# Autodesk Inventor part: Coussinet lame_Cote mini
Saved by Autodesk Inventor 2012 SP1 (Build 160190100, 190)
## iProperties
Created: 2014-12
Part Number: Coussinet lame_Cote mini
Material: Default
Document SubType Name: Modeling
Designer: Bruno
Density: 1 g/cm^3
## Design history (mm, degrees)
node "Coussinet lame_Cote mini1"
node "Coussinet lame_Cote mini"
node "Base1"
